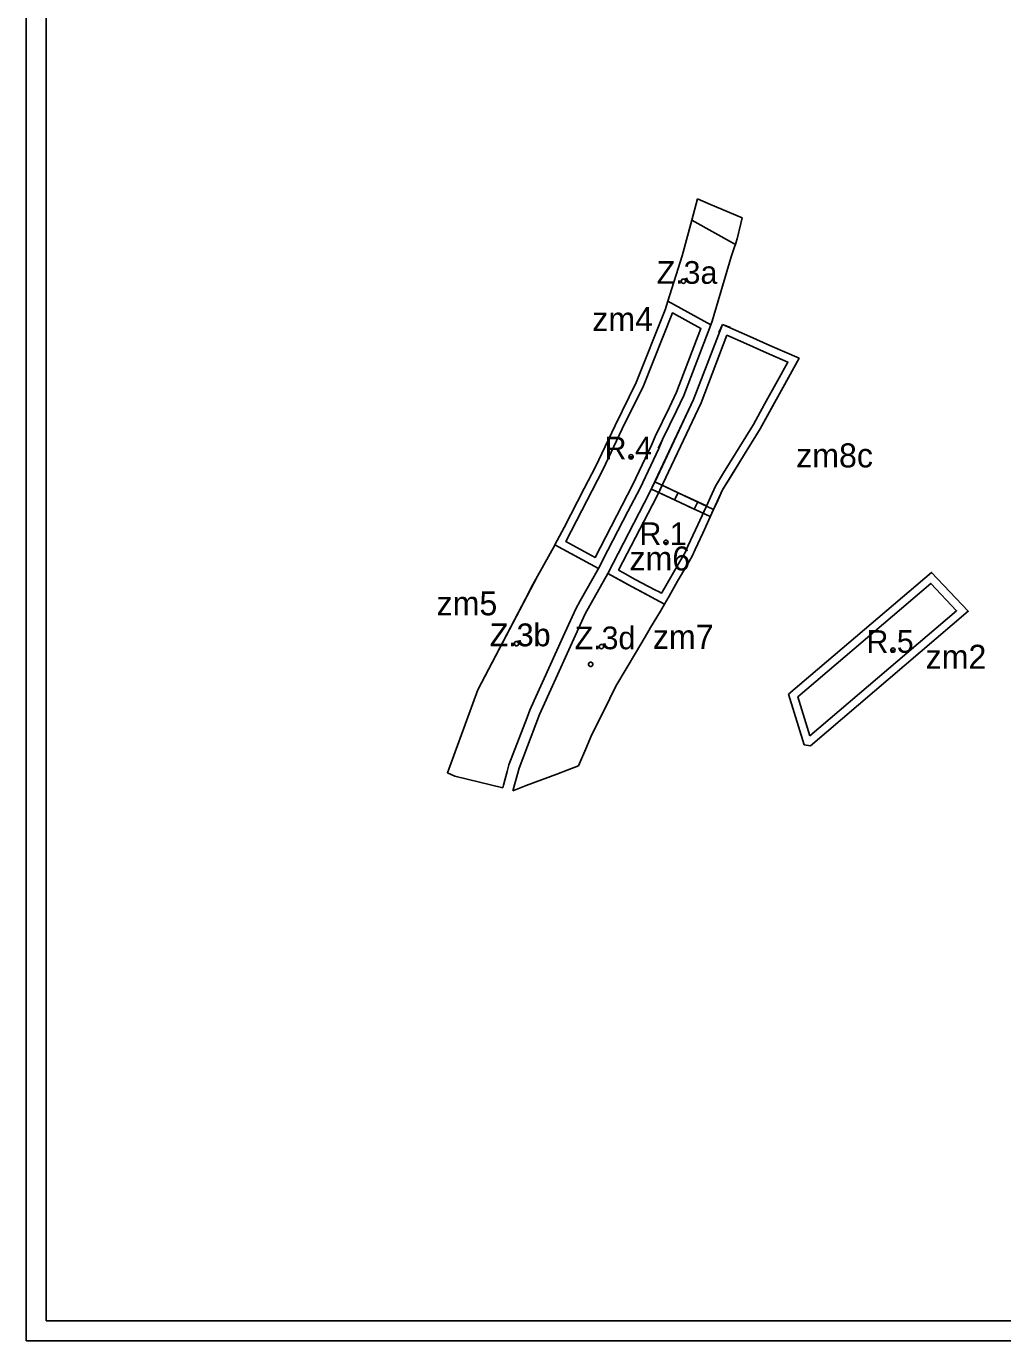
# Model space of a CAD drawing. Extents: x -555210 to -552521, y -1185897 to -1183927.
# Drawn here: x -555210 to -554479, y -1185897 to -1184912 of the extents above; entities that cross this region are included whole.
import ezdxf

# ---------------------------------------------------------------- set-up
doc = ezdxf.new("R2010")
doc.units = 0
for name, color, linetype in [('LEG_2b', 7, 'Continuous'), ('ram_5000', 7, 'Continuous'), ('REGULATIV_navrh', 7, 'Continuous'), ('stav_DS', 7, 'Continuous'), ('stav_DSg', 7, 'Continuous'), ('stav_OV', 7, 'Continuous'), ('stav_PU', 7, 'Continuous'), ('stav_SV', 7, 'Continuous'), ('stav_SX', 7, 'Continuous'), ('stav_VL', 7, 'Continuous'), ('stav_ZZ', 7, 'Continuous')]:
    doc.layers.add(name, color=color, linetype=linetype)

msp = doc.modelspace()

# ---------------------------------------------------------------- linework, layer by layer
at = {"layer": 'LEG_2b'}
for centre in [(-554717.64, -1185103.21), (-554756.84, -1185234.83), (-554730.77, -1185298.92), (-554842.76, -1185374.9), (-554842.55, -1185374.8), (-554779.07, -1185377.11), (-554779.07, -1185377.11), (-554560.71, -1185379.73)]:
    msp.add_circle(centre, 1.64, dxfattribs=at)
at = {"layer": 'ram_5000'}
for p, q in [((-554707.18, -1185041.55), (-554711.41, -1185057.49)), ((-554711.41, -1185057.49), (-554718.48, -1185084.14)), ((-554673.61, -1185055.83), (-554678.5, -1185053.7)), ((-554677.33, -1185071.44), (-554674.57, -1185059.86)), ((-554674.57, -1185059.86), (-554673.61, -1185055.83)), ((-554681.76, -1185084.97), (-554679.31, -1185077.48)), ((-554679.31, -1185077.48), (-554678.73, -1185075.72)), ((-554678.73, -1185075.72), (-554678.65, -1185075.47)), ((-554678.65, -1185075.47), (-554677.33, -1185071.44)), ((-554718.48, -1185084.14), (-554729.32, -1185118.29)), ((-554696.07, -1185133.1), (-554681.76, -1185084.97)), ((-554729.32, -1185118.29), (-554731.33, -1185124.63)), ((-554731.33, -1185124.63), (-554753.06, -1185179.2)), ((-554717.35, -1185188.83), (-554697.1, -1185135.79)), ((-554697.1, -1185135.79), (-554696.07, -1185133.1)), ((-554753.06, -1185179.2), (-554768.86, -1185211.34)), ((-554722.73, -1185200.26), (-554717.35, -1185188.83)), ((-554733.33, -1185221.96), (-554722.73, -1185200.26)), ((-554768.86, -1185211.34), (-554778.8, -1185232.44)), ((-554736.6, -1185228.38), (-554733.33, -1185221.96)), ((-554778.8, -1185232.44), (-554783.25, -1185241.89)), ((-554746.09, -1185249.82), (-554736.11, -1185228.65)), ((-554736.11, -1185228.65), (-554736.6, -1185228.38)), ((-554783.25, -1185241.89), (-554791.87, -1185258.48)), ((-554750.09, -1185258.31), (-554746.09, -1185249.82)), ((-554791.87, -1185258.48), (-554807.06, -1185287.73)), ((-554759.23, -1185275.9), (-554750.09, -1185258.31)), ((-554774.2, -1185304.73), (-554759.23, -1185275.9)), ((-554807.06, -1185287.73), (-554813.83, -1185300.75)), ((-554813.94, -1185300.96), (-554826.92, -1185324.2)), ((-554813.83, -1185300.75), (-554813.94, -1185300.96)), ((-554813.83, -1185300.75), (-554781.34, -1185318.48)), ((-554781.34, -1185318.48), (-554813.83, -1185300.75)), ((-554781.34, -1185318.48), (-554774.2, -1185304.73)), ((-554794.88, -1185342.72), (-554781.36, -1185318.51)), ((-554781.36, -1185318.51), (-554781.34, -1185318.48)), ((-554833.18, -1185336.15), (-554871.53, -1185409.38)), ((-554798.33, -1185348.89), (-554794.88, -1185342.72)), ((-554807.68, -1185369.52), (-554798.33, -1185348.89)), ((-554823.22, -1185403.79), (-554807.68, -1185369.52)), ((-554829.45, -1185417.54), (-554823.22, -1185403.79)), ((-554834.79, -1185430.19), (-554832.74, -1185424.8)), ((-554832.74, -1185424.8), (-554829.45, -1185417.54)), ((-554848.3, -1185465.81), (-554834.79, -1185430.19)), ((-554888.92, -1185474.12), (-554853.01, -1185482.98)), ((-554852.46, -1185480.97), (-554849.67, -1185470.78)), ((-554849.67, -1185470.78), (-554848.3, -1185465.81)), ((-554853.01, -1185482.98), (-554852.47, -1185480.98)), ((-554852.47, -1185480.98), (-554852.46, -1185480.97))]:
    msp.add_line(p, q, dxfattribs=at)
for points in [[(-554678.5, -1185053.7), (-554699.04, -1185044.99), (-554707.18, -1185041.55)], [(-554826.92, -1185324.2), (-554831.39, -1185332.2), (-554833.18, -1185336.15)], [(-554871.53, -1185409.38), (-554894.36, -1185471.66), (-554888.92, -1185474.12)]]:
    msp.add_lwpolyline(points, dxfattribs=at)
msp.add_lwpolyline([(-554638.92, -1185412.79), (-554531.78, -1185321.49), (-554504.31, -1185350.64), (-554622.56, -1185451.39), (-554627.18, -1185450.64)], close=True, dxfattribs=at)
at = {"layer": 'REGULATIV_navrh'}
for p, q in [((-554688.49, -1185135.67), (-554709.98, -1185191.97)), ((-554742.92, -1185261.86), (-554709.98, -1185191.97)), ((-554774.32, -1185322.31), (-554742.92, -1185261.86))]:
    msp.add_line(p, q, dxfattribs=at)
for points in [[(-554688.39, -1185135.59), (-554667.86, -1185144.71), (-554652.87, -1185151.49), (-554630.97, -1185160.97)], [(-554694.99, -1185274.23), (-554703.22, -1185292.14), (-554708.82, -1185304.31), (-554711.08, -1185309.23), (-554715.19, -1185316.37), (-554721.98, -1185328.15), (-554728.42, -1185339.33), (-554731.79, -1185345.18), (-554741.42, -1185340.01), (-554756.64, -1185331.95), (-554774.32, -1185322.31)]]:
    msp.add_lwpolyline(points, dxfattribs=at)
at = {"layer": 'stav_DS'}
msp.add_lwpolyline([(-554888.92, -1185474.12), (-554894.36, -1185471.66), (-554871.53, -1185409.38), (-554826.92, -1185324.2)], dxfattribs=at)
at = {"layer": 'stav_DSg'}
for q in [(-554691.1, -1185141.62), (-554682.42, -1185137.99)]:
    msp.add_line((-554688.49, -1185135.67), q, dxfattribs=at)
at = {"layer": 'stav_OV'}
for p, q in [((-555209.81, -1183926.97), (-555209.81, -1185897.32)), ((-555194.81, -1185882.32), (-555194.81, -1183941.97)), ((-553535.77, -1185882.32), (-555194.81, -1185882.32)), ((-555209.81, -1185897.32), (-552520.77, -1185897.32))]:
    msp.add_line(p, q, dxfattribs=at)
at = {"layer": 'stav_SX'}
for p, q in [((-554813.94, -1185300.96), (-554826.92, -1185324.2)), ((-554813.83, -1185300.75), (-554813.94, -1185300.96)), ((-554781.34, -1185318.48), (-554813.83, -1185300.75)), ((-554794.88, -1185342.72), (-554781.36, -1185318.51)), ((-554774.32, -1185322.31), (-554791.18, -1185352.5)), ((-554781.36, -1185318.51), (-554781.34, -1185318.48)), ((-554765.45, -1185327.15), (-554774.32, -1185322.31)), ((-554833.18, -1185336.15), (-554871.53, -1185409.38)), ((-554756.64, -1185331.95), (-554765.45, -1185327.15)), ((-554746.53, -1185337.24), (-554756.64, -1185331.95)), ((-554798.33, -1185348.89), (-554794.88, -1185342.72)), ((-554741.42, -1185340.01), (-554746.53, -1185337.24)), ((-554739.23, -1185341.16), (-554741.42, -1185340.01)), ((-554731.79, -1185345.18), (-554739.23, -1185341.16)), ((-554734.88, -1185350.42), (-554731.79, -1185345.18)), ((-554791.18, -1185352.5), (-554825.35, -1185427.87)), ((-554807.68, -1185369.52), (-554798.33, -1185348.89)), ((-554742.18, -1185362.81), (-554734.88, -1185350.42)), ((-554744.55, -1185366.82), (-554742.18, -1185362.81)), ((-554823.22, -1185403.79), (-554807.68, -1185369.52)), ((-554747.05, -1185371.06), (-554744.55, -1185366.82)), ((-554768.14, -1185406.83), (-554760.45, -1185393.79)), ((-554829.45, -1185417.54), (-554823.22, -1185403.79)), ((-554772.69, -1185415.93), (-554768.14, -1185406.83)), ((-554834.79, -1185430.19), (-554832.74, -1185424.8)), ((-554832.74, -1185424.8), (-554829.45, -1185417.54)), ((-554786.97, -1185444.66), (-554772.69, -1185415.93)), ((-554848.3, -1185465.81), (-554834.79, -1185430.19)), ((-554825.35, -1185427.87), (-554840.69, -1185468.29)), ((-554790.07, -1185451.89), (-554786.97, -1185444.66)), ((-554796.32, -1185466.44), (-554790.07, -1185451.89)), ((-554790.07, -1185451.89), (-554790.07, -1185451.89)), ((-554888.92, -1185474.12), (-554853.01, -1185482.98)), ((-554852.46, -1185480.97), (-554849.67, -1185470.78)), ((-554849.67, -1185470.78), (-554848.3, -1185465.81)), ((-554840.69, -1185468.29), (-554845.3, -1185485.1)), ((-554835.3, -1185481.29), (-554812.49, -1185472.6)), ((-554812.49, -1185472.6), (-554804.61, -1185469.6)), ((-554804.61, -1185469.6), (-554796.32, -1185466.44)), ((-554853.01, -1185482.98), (-554852.47, -1185480.98)), ((-554852.47, -1185480.98), (-554852.46, -1185480.97)), ((-554845.3, -1185485.1), (-554835.3, -1185481.29))]:
    msp.add_line(p, q, dxfattribs=at)
for points in [[(-554826.92, -1185324.2), (-554831.39, -1185332.2), (-554833.18, -1185336.15)], [(-554760.45, -1185393.79), (-554752.81, -1185380.83), (-554747.05, -1185371.06)], [(-554871.53, -1185409.38), (-554894.36, -1185471.66), (-554888.92, -1185474.12)]]:
    msp.add_lwpolyline(points, dxfattribs=at)
for centre, start, end in [((-554787.11, -1185390.4), 164.64151, 347.25747), ((-554787.09, -1185390.32), 344.64151, 167.25747)]:
    msp.add_arc(centre, 1.64, start, end, dxfattribs=at)
at = {"layer": 'stav_VL'}
for p, q in [((-554729.32, -1185118.29), (-554731.33, -1185124.63)), ((-554729.32, -1185118.29), (-554731.33, -1185124.63)), ((-554697.1, -1185135.79), (-554729.32, -1185118.29)), ((-554697.1, -1185135.79), (-554729.32, -1185118.29)), ((-554731.33, -1185124.63), (-554753.06, -1185179.2)), ((-554731.33, -1185124.63), (-554753.06, -1185179.2)), ((-554717.35, -1185188.83), (-554697.1, -1185135.79)), ((-554717.35, -1185188.83), (-554697.1, -1185135.79)), ((-554688.49, -1185135.67), (-554709.98, -1185191.97)), ((-554688.49, -1185135.67), (-554709.98, -1185191.97)), ((-554667.86, -1185144.71), (-554688.49, -1185135.67)), ((-554667.86, -1185144.71), (-554688.49, -1185135.67)), ((-554704.46, -1185194.32), (-554685.13, -1185143.69)), ((-554704.46, -1185194.32), (-554685.13, -1185143.69)), ((-554685.13, -1185143.69), (-554670.3, -1185150.19)), ((-554685.13, -1185143.69), (-554670.3, -1185150.19)), ((-554652.87, -1185151.49), (-554667.86, -1185144.71)), ((-554652.87, -1185151.49), (-554667.86, -1185144.71)), ((-554670.3, -1185150.19), (-554655.3, -1185156.98)), ((-554670.3, -1185150.19), (-554655.3, -1185156.98)), ((-554630.97, -1185160.97), (-554652.87, -1185151.49)), ((-554630.97, -1185160.97), (-554652.87, -1185151.49)), ((-554641.88, -1185180.77), (-554630.97, -1185160.97)), ((-554641.88, -1185180.77), (-554630.97, -1185160.97)), ((-554753.06, -1185179.2), (-554768.86, -1185211.34)), ((-554753.06, -1185179.2), (-554768.86, -1185211.34)), ((-554651.54, -1185198.32), (-554641.88, -1185180.77)), ((-554651.54, -1185198.32), (-554641.88, -1185180.77)), ((-554709.98, -1185191.97), (-554738.91, -1185253.34)), ((-554709.98, -1185191.97), (-554738.91, -1185253.34)), ((-554722.73, -1185200.26), (-554717.35, -1185188.83)), ((-554722.73, -1185200.26), (-554717.35, -1185188.83)), ((-554660.04, -1185213.75), (-554651.54, -1185198.32)), ((-554660.04, -1185213.75), (-554651.54, -1185198.32)), ((-554733.33, -1185221.96), (-554722.73, -1185200.26)), ((-554733.33, -1185221.96), (-554722.73, -1185200.26)), ((-554768.86, -1185211.34), (-554778.8, -1185232.44)), ((-554768.86, -1185211.34), (-554778.8, -1185232.44)), ((-554671.87, -1185232.89), (-554661.31, -1185215.81)), ((-554671.87, -1185232.89), (-554661.31, -1185215.81)), ((-554661.31, -1185215.81), (-554660.04, -1185213.75)), ((-554661.31, -1185215.81), (-554660.04, -1185213.75)), ((-554736.11, -1185228.65), (-554733.33, -1185221.96)), ((-554736.11, -1185228.65), (-554733.33, -1185221.96)), ((-554778.8, -1185232.44), (-554783.25, -1185241.89)), ((-554778.8, -1185232.44), (-554783.25, -1185241.89)), ((-554746.09, -1185249.82), (-554736.11, -1185228.65)), ((-554746.09, -1185249.82), (-554736.11, -1185228.65)), ((-554682.43, -1185249.97), (-554671.87, -1185232.89)), ((-554682.43, -1185249.97), (-554671.87, -1185232.89)), ((-554783.25, -1185241.89), (-554791.87, -1185258.48)), ((-554783.25, -1185241.89), (-554791.87, -1185258.48)), ((-554687.53, -1185246.82), (-554693.73, -1185256.85)), ((-554687.53, -1185246.82), (-554693.73, -1185256.85)), ((-554738.91, -1185253.34), (-554742.92, -1185261.86)), ((-554738.91, -1185253.34), (-554742.92, -1185261.86)), ((-554739.02, -1185253.58), (-554694.99, -1185274.23)), ((-554733.58, -1185256.13), (-554736.14, -1185261.55)), ((-554721.59, -1185261.75), (-554733.58, -1185256.13)), ((-554693.73, -1185256.85), (-554697.42, -1185265.03)), ((-554693.73, -1185256.85), (-554697.42, -1185265.03)), ((-554688.42, -1185259.67), (-554682.43, -1185249.97)), ((-554688.42, -1185259.67), (-554682.43, -1185249.97)), ((-554791.87, -1185258.48), (-554807.06, -1185287.73)), ((-554791.87, -1185258.48), (-554807.06, -1185287.73)), ((-554742.92, -1185261.86), (-554774.32, -1185322.31)), ((-554742.92, -1185261.86), (-554774.32, -1185322.31)), ((-554741.56, -1185259.01), (-554697.54, -1185279.66)), ((-554736.14, -1185261.55), (-554724.27, -1185267.12)), ((-554724.27, -1185267.12), (-554721.59, -1185261.75)), ((-554721.59, -1185261.75), (-554724.27, -1185267.12)), ((-554724.27, -1185267.12), (-554709.53, -1185274.03)), ((-554706.92, -1185268.63), (-554721.59, -1185261.75)), ((-554697.42, -1185265.03), (-554700.45, -1185271.74)), ((-554697.42, -1185265.03), (-554700.45, -1185271.74)), ((-554694.99, -1185274.23), (-554691.95, -1185267.5)), ((-554694.99, -1185274.23), (-554691.95, -1185267.5)), ((-554691.95, -1185267.5), (-554688.42, -1185259.67)), ((-554691.95, -1185267.5), (-554688.42, -1185259.67)), ((-554774.2, -1185304.73), (-554759.23, -1185275.9)), ((-554774.2, -1185304.73), (-554759.23, -1185275.9)), ((-554709.53, -1185274.03), (-554706.92, -1185268.63)), ((-554706.92, -1185268.63), (-554709.53, -1185274.03)), ((-554709.53, -1185274.03), (-554702.93, -1185277.13)), ((-554700.45, -1185271.74), (-554708.67, -1185289.63)), ((-554700.45, -1185271.74), (-554708.67, -1185289.63)), ((-554700.42, -1185271.68), (-554706.92, -1185268.63)), ((-554703.22, -1185292.14), (-554694.99, -1185274.23)), ((-554703.22, -1185292.14), (-554694.99, -1185274.23)), ((-554702.93, -1185277.13), (-554700.45, -1185271.74)), ((-554700.45, -1185271.74), (-554700.42, -1185271.68)), ((-554807.06, -1185287.73), (-554813.83, -1185300.75)), ((-554807.06, -1185287.73), (-554813.83, -1185300.75)), ((-554708.67, -1185289.63), (-554714.27, -1185301.8)), ((-554708.67, -1185289.63), (-554714.27, -1185301.8)), ((-554708.82, -1185304.31), (-554703.22, -1185292.14)), ((-554708.82, -1185304.31), (-554703.22, -1185292.14)), ((-554813.83, -1185300.75), (-554781.34, -1185318.48)), ((-554813.83, -1185300.75), (-554781.34, -1185318.48)), ((-554781.34, -1185318.48), (-554774.2, -1185304.73)), ((-554781.34, -1185318.48), (-554774.2, -1185304.73)), ((-554716.42, -1185306.48), (-554720.39, -1185313.38)), ((-554716.42, -1185306.48), (-554720.39, -1185313.38)), ((-554714.27, -1185301.8), (-554716.42, -1185306.48)), ((-554714.27, -1185301.8), (-554716.42, -1185306.48)), ((-554711.08, -1185309.23), (-554708.82, -1185304.31)), ((-554711.08, -1185309.23), (-554708.82, -1185304.31)), ((-554721.98, -1185328.15), (-554715.19, -1185316.37)), ((-554721.98, -1185328.15), (-554715.19, -1185316.37)), ((-554715.19, -1185316.37), (-554711.08, -1185309.23)), ((-554715.19, -1185316.37), (-554711.08, -1185309.23)), ((-554531.78, -1185321.49), (-554638.92, -1185412.79)), ((-554504.31, -1185350.64), (-554531.78, -1185321.49)), ((-554756.64, -1185331.95), (-554746.53, -1185337.24)), ((-554756.64, -1185331.95), (-554746.53, -1185337.24)), ((-554743.71, -1185331.94), (-554753.81, -1185326.66)), ((-554743.71, -1185331.94), (-554753.81, -1185326.66)), ((-554728.42, -1185339.33), (-554721.98, -1185328.15)), ((-554728.42, -1185339.33), (-554721.98, -1185328.15)), ((-554746.53, -1185337.24), (-554741.42, -1185340.01)), ((-554746.53, -1185337.24), (-554741.42, -1185340.01)), ((-554741.42, -1185340.01), (-554739.23, -1185341.16)), ((-554741.42, -1185340.01), (-554739.23, -1185341.16)), ((-554739.23, -1185341.16), (-554731.79, -1185345.18)), ((-554739.23, -1185341.16), (-554731.79, -1185345.18)), ((-554731.79, -1185345.18), (-554728.42, -1185339.33)), ((-554731.79, -1185345.18), (-554728.42, -1185339.33)), ((-554622.56, -1185451.39), (-554504.31, -1185350.64))]:
    msp.add_line(p, q, dxfattribs=at)
for points in [[(-554755.47, -1185255.65), (-554783.85, -1185310.28), (-554805.8, -1185298.3), (-554777.88, -1185244.55), (-554763.45, -1185213.94), (-554747.57, -1185181.64), (-554725.82, -1185127.02), (-554704.58, -1185138.55), (-554722.87, -1185186.48), (-554728.14, -1185197.66), (-554738.8, -1185219.49), (-554741.6, -1185226.21), (-554755.47, -1185255.65)], [(-554755.47, -1185255.65), (-554783.85, -1185310.28), (-554805.8, -1185298.3), (-554777.88, -1185244.55), (-554763.45, -1185213.94), (-554747.57, -1185181.64), (-554725.82, -1185127.02), (-554704.58, -1185138.55), (-554722.87, -1185186.48), (-554728.14, -1185197.66), (-554738.8, -1185219.49), (-554741.6, -1185226.21), (-554755.47, -1185255.65)], [(-554655.3, -1185156.98), (-554639.41, -1185163.85), (-554647.14, -1185177.88), (-554656.8, -1185195.43), (-554665.22, -1185210.73), (-554666.42, -1185212.66), (-554687.53, -1185246.82)], [(-554655.3, -1185156.98), (-554639.41, -1185163.85), (-554647.14, -1185177.88), (-554656.8, -1185195.43), (-554665.22, -1185210.73), (-554666.42, -1185212.66), (-554687.53, -1185246.82)], [(-554766.29, -1185319.86), (-554737.54, -1185264.52), (-554704.46, -1185194.32)], [(-554766.29, -1185319.86), (-554737.54, -1185264.52), (-554704.46, -1185194.32)], [(-554759.23, -1185275.9), (-554750.09, -1185258.31), (-554746.09, -1185249.82)], [(-554759.23, -1185275.9), (-554750.09, -1185258.31), (-554746.09, -1185249.82)], [(-554720.39, -1185313.38), (-554727.18, -1185325.15), (-554733.62, -1185336.34), (-554734.07, -1185337.13), (-554736.41, -1185335.86)], [(-554720.39, -1185313.38), (-554727.18, -1185325.15), (-554733.62, -1185336.34), (-554734.07, -1185337.13), (-554736.41, -1185335.86)], [(-554774.32, -1185322.31), (-554765.45, -1185327.15), (-554756.64, -1185331.95)], [(-554774.32, -1185322.31), (-554765.45, -1185327.15), (-554756.64, -1185331.95)], [(-554753.81, -1185326.66), (-554762.58, -1185321.88), (-554766.29, -1185319.86)], [(-554753.81, -1185326.66), (-554762.58, -1185321.88), (-554766.29, -1185319.86)], [(-554736.41, -1185335.86), (-554738.6, -1185334.72), (-554743.71, -1185331.94)], [(-554736.41, -1185335.86), (-554738.6, -1185334.72), (-554743.71, -1185331.94)], [(-554622.99, -1185443.89), (-554632.02, -1185414.79), (-554532.23, -1185329.76), (-554513, -1185350.16), (-554622.99, -1185443.89)], [(-554638.92, -1185412.79), (-554627.18, -1185450.64), (-554622.56, -1185451.39)]]:
    msp.add_lwpolyline(points, dxfattribs=at)
msp.add_lwpolyline([(-554688.49, -1185135.67), (-554709.98, -1185191.97), (-554739.02, -1185253.58), (-554694.99, -1185274.23), (-554688.42, -1185259.67), (-554660.04, -1185213.75), (-554630.97, -1185160.97), (-554652.87, -1185151.49), (-554667.86, -1185144.71)], close=True, dxfattribs=at)
at = {"layer": 'stav_ZZ'}
for p, q in [((-554711.41, -1185057.49), (-554718.48, -1185084.14)), ((-554711.41, -1185057.49), (-554678.73, -1185075.72)), ((-554681.76, -1185084.97), (-554679.31, -1185077.48)), ((-554679.31, -1185077.48), (-554678.65, -1185075.47)), ((-554718.48, -1185084.14), (-554729.32, -1185118.29)), ((-554696.07, -1185133.1), (-554681.76, -1185084.97)), ((-554729.32, -1185118.29), (-554697.1, -1185135.79)), ((-554697.1, -1185135.79), (-554696.07, -1185133.1)), ((-554813.94, -1185300.96), (-554826.92, -1185324.2)), ((-554813.83, -1185300.75), (-554813.94, -1185300.96)), ((-554781.34, -1185318.48), (-554813.83, -1185300.75)), ((-554794.88, -1185342.72), (-554781.36, -1185318.51)), ((-554774.32, -1185322.31), (-554791.18, -1185352.5)), ((-554781.36, -1185318.51), (-554781.34, -1185318.48)), ((-554833.18, -1185336.15), (-554871.53, -1185409.38)), ((-554746.53, -1185337.24), (-554756.64, -1185331.95)), ((-554798.33, -1185348.89), (-554794.88, -1185342.72)), ((-554731.79, -1185345.18), (-554739.23, -1185341.16)), ((-554734.88, -1185350.42), (-554731.79, -1185345.18)), ((-554791.18, -1185352.5), (-554825.35, -1185427.87)), ((-554807.68, -1185369.52), (-554798.33, -1185348.89)), ((-554742.18, -1185362.81), (-554734.88, -1185350.42)), ((-554744.55, -1185366.82), (-554742.18, -1185362.81)), ((-554823.22, -1185403.79), (-554807.68, -1185369.52)), ((-554752.81, -1185380.83), (-554747.05, -1185371.06)), ((-554747.05, -1185371.06), (-554744.55, -1185366.82)), ((-554760.45, -1185393.79), (-554752.81, -1185380.83)), ((-554768.14, -1185406.83), (-554760.45, -1185393.79)), ((-554829.45, -1185417.54), (-554823.22, -1185403.79)), ((-554772.69, -1185415.93), (-554768.14, -1185406.83)), ((-554834.79, -1185430.19), (-554832.74, -1185424.8)), ((-554832.74, -1185424.8), (-554829.45, -1185417.54)), ((-554786.97, -1185444.66), (-554772.69, -1185415.93)), ((-554848.3, -1185465.81), (-554834.79, -1185430.19)), ((-554825.35, -1185427.87), (-554840.69, -1185468.29)), ((-554790.07, -1185451.89), (-554786.97, -1185444.66)), ((-554796.32, -1185466.44), (-554790.07, -1185451.89)), ((-554790.07, -1185451.89), (-554790.07, -1185451.89)), ((-554888.92, -1185474.12), (-554853.01, -1185482.98)), ((-554852.46, -1185480.97), (-554849.67, -1185470.78)), ((-554849.67, -1185470.78), (-554848.3, -1185465.81)), ((-554840.69, -1185468.29), (-554845.3, -1185485.1)), ((-554835.3, -1185481.29), (-554812.49, -1185472.6)), ((-554812.49, -1185472.6), (-554804.61, -1185469.6)), ((-554804.61, -1185469.6), (-554796.32, -1185466.44)), ((-554853.01, -1185482.98), (-554852.47, -1185480.98)), ((-554852.47, -1185480.98), (-554852.46, -1185480.97)), ((-554845.3, -1185485.1), (-554835.3, -1185481.29))]:
    msp.add_line(p, q, dxfattribs=at)
for points in [[(-554826.92, -1185324.2), (-554831.39, -1185332.2), (-554833.18, -1185336.15)], [(-554756.64, -1185331.95), (-554765.45, -1185327.15), (-554774.32, -1185322.31)], [(-554739.23, -1185341.16), (-554741.42, -1185340.01), (-554746.53, -1185337.24)], [(-554871.53, -1185409.38), (-554894.36, -1185471.66), (-554888.92, -1185474.12)]]:
    msp.add_lwpolyline(points, dxfattribs=at)

# ---------------------------------------------------------------- texts
at = {"layer": 'stav_PU'}
for s, p in [('Z.3a', (-554737.7, -1185105.15)), ('R.4', (-554776.66, -1185236.84)), ('R.1', (-554750.54, -1185300.96)), ('Z.3b', (-554862.81, -1185376.84)), ('Z.3b', (-554862.61, -1185376.73)), ('Z.3d', (-554799.13, -1185379.05)), ('Z.3d', (-554799.13, -1185379.05)), ('R.5', (-554580.54, -1185381.75))]:
    msp.add_text(s, height=17, dxfattribs=at).set_placement(p)
at = {"layer": 'stav_SV'}
for s, p in [('zm4', (-554785.89, -1185140.63)), ('zm8c', (-554633.17, -1185242.78)), ('zm6', (-554758.05, -1185320.02)), ('zm5', (-554902.51, -1185353.65)), ('zm7', (-554740.52, -1185378.76)), ('zm2', (-554536.21, -1185393.72))]:
    msp.add_text(s, height=18, dxfattribs=at).set_placement(p)

doc.saveas('drawing.dxf')
